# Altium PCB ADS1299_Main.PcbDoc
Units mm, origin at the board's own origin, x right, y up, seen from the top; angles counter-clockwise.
Board outline 156.34 x 83.19 mm, 6 copper layers (Top Layer, GND, AVSS, AVDD, DVDD, Bottom Layer), stack 0.816 mm thick; 64 components, 110 nets, 548 pads, 68 vias.
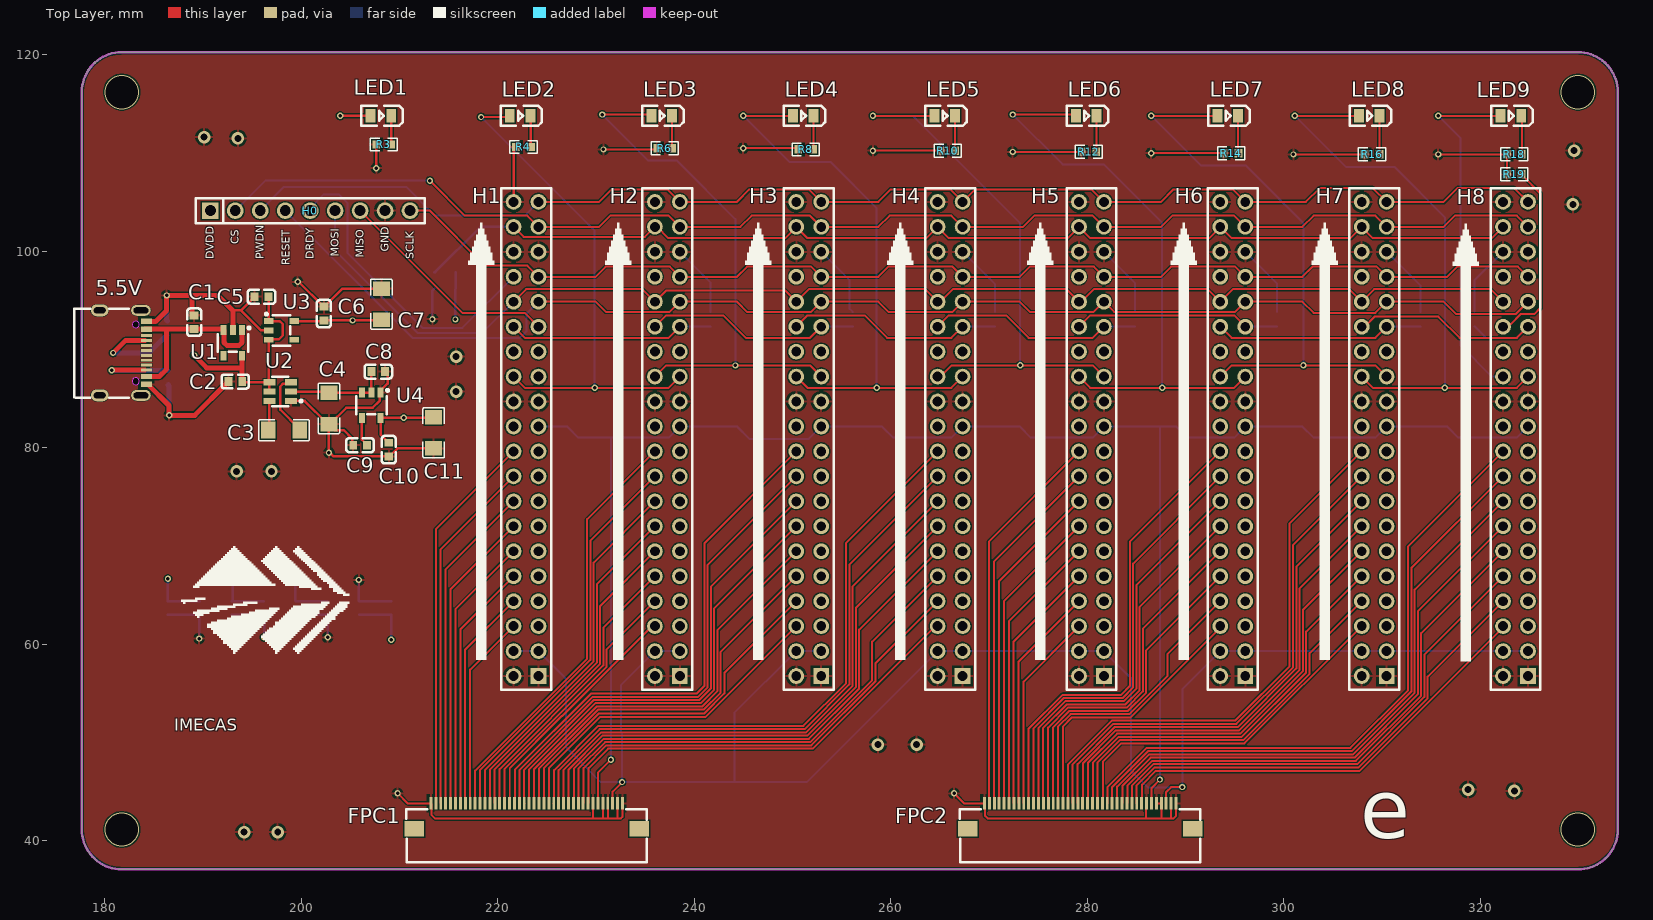
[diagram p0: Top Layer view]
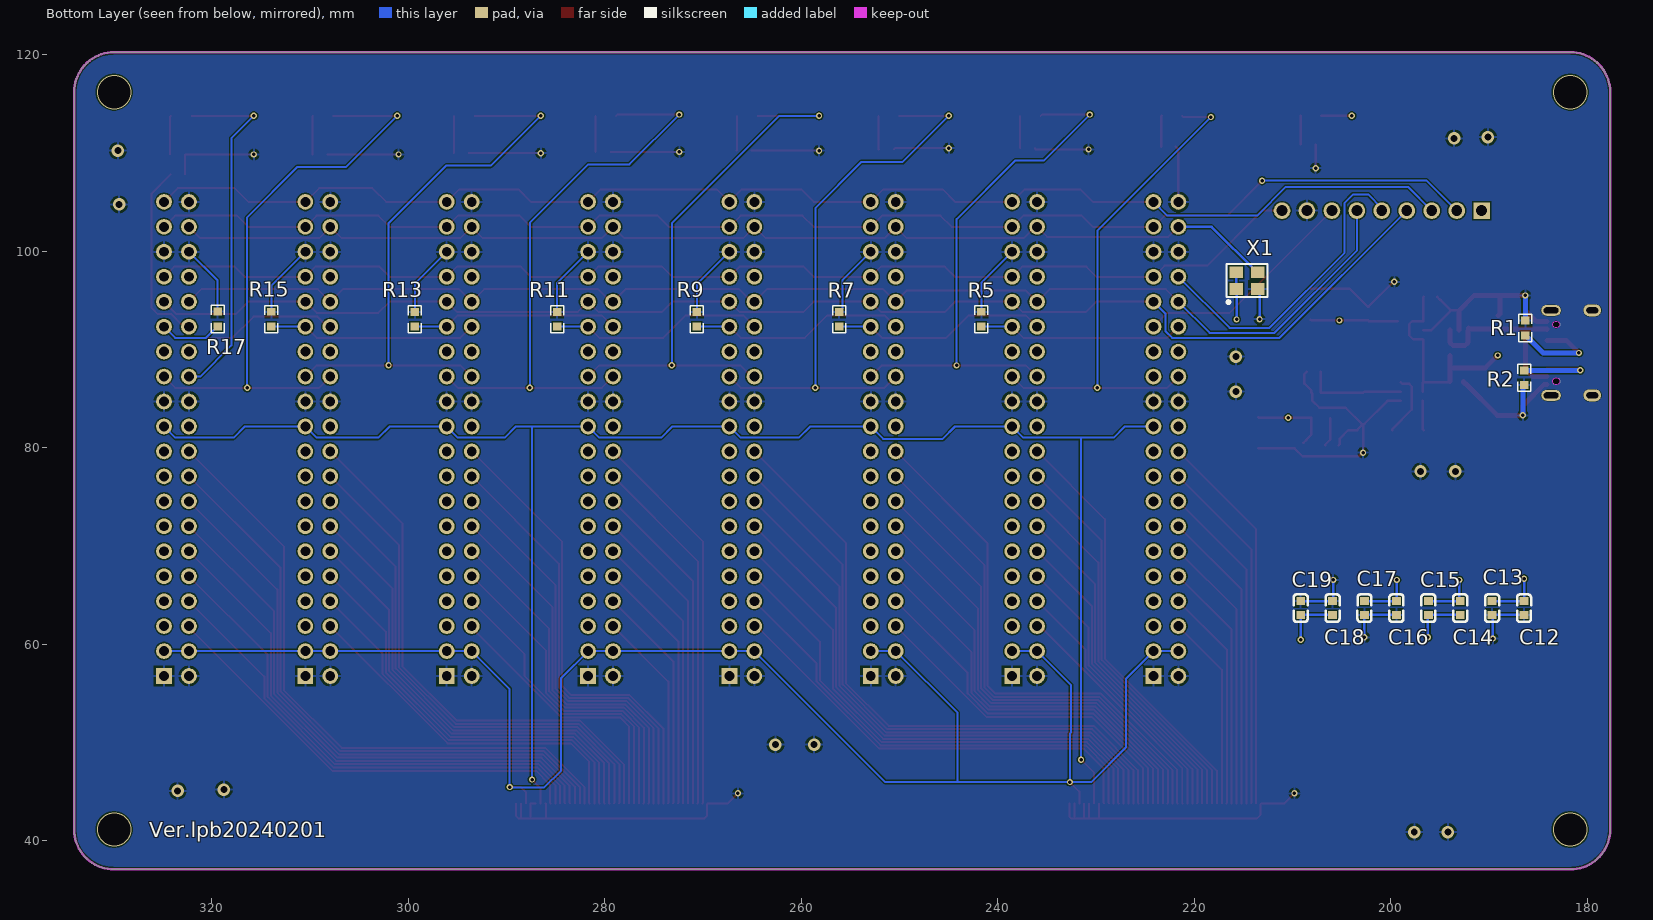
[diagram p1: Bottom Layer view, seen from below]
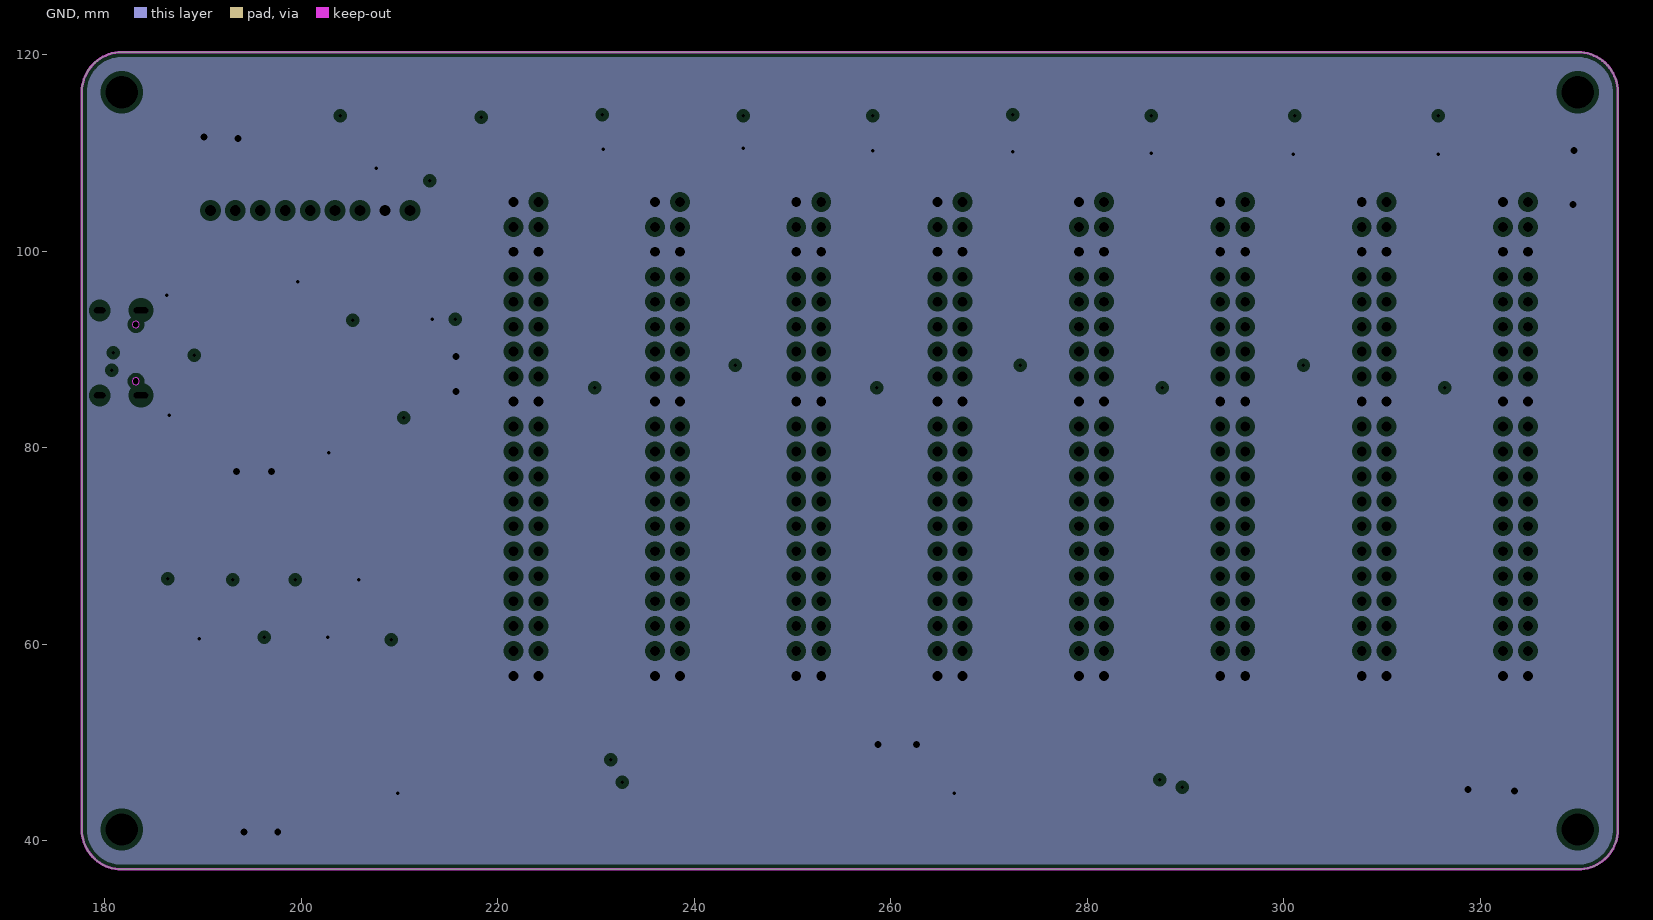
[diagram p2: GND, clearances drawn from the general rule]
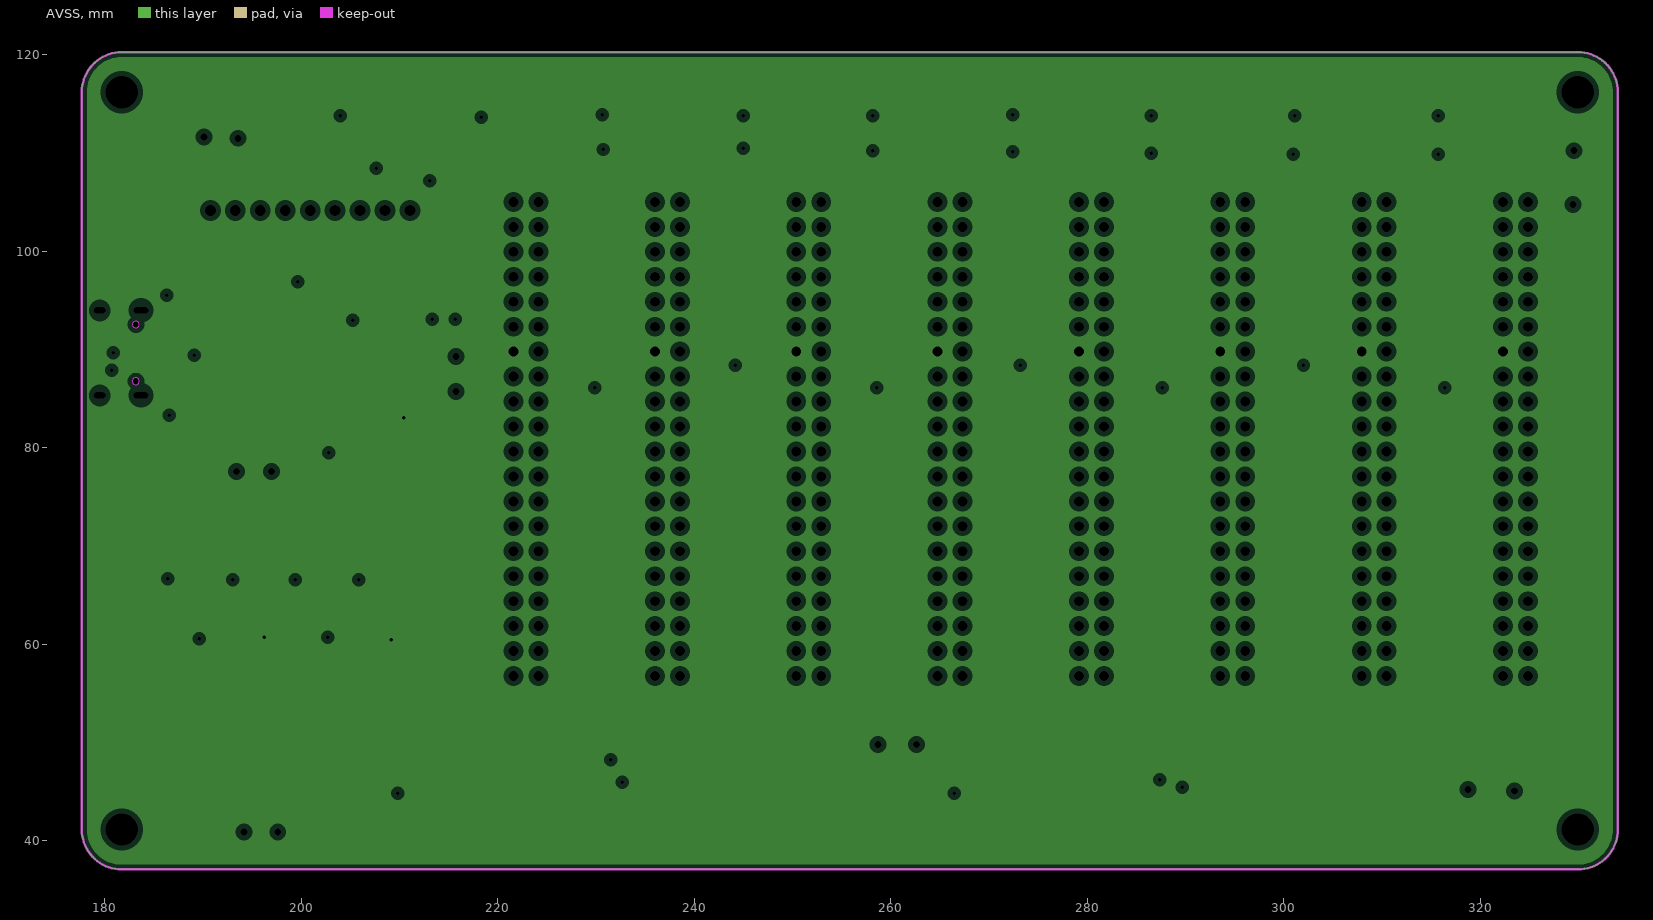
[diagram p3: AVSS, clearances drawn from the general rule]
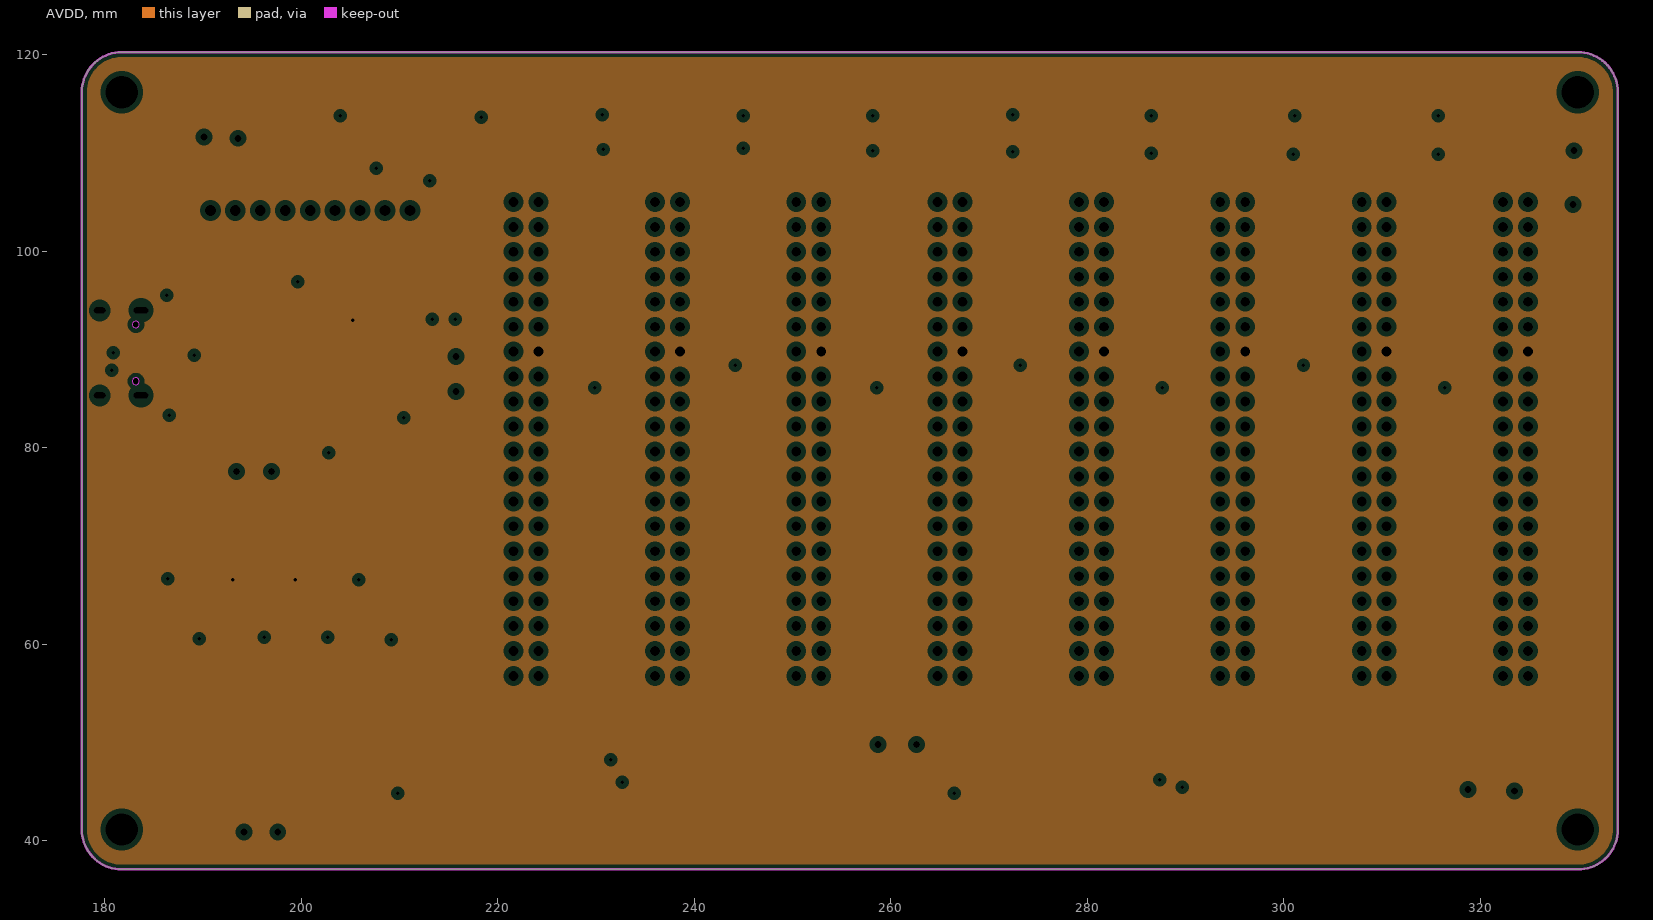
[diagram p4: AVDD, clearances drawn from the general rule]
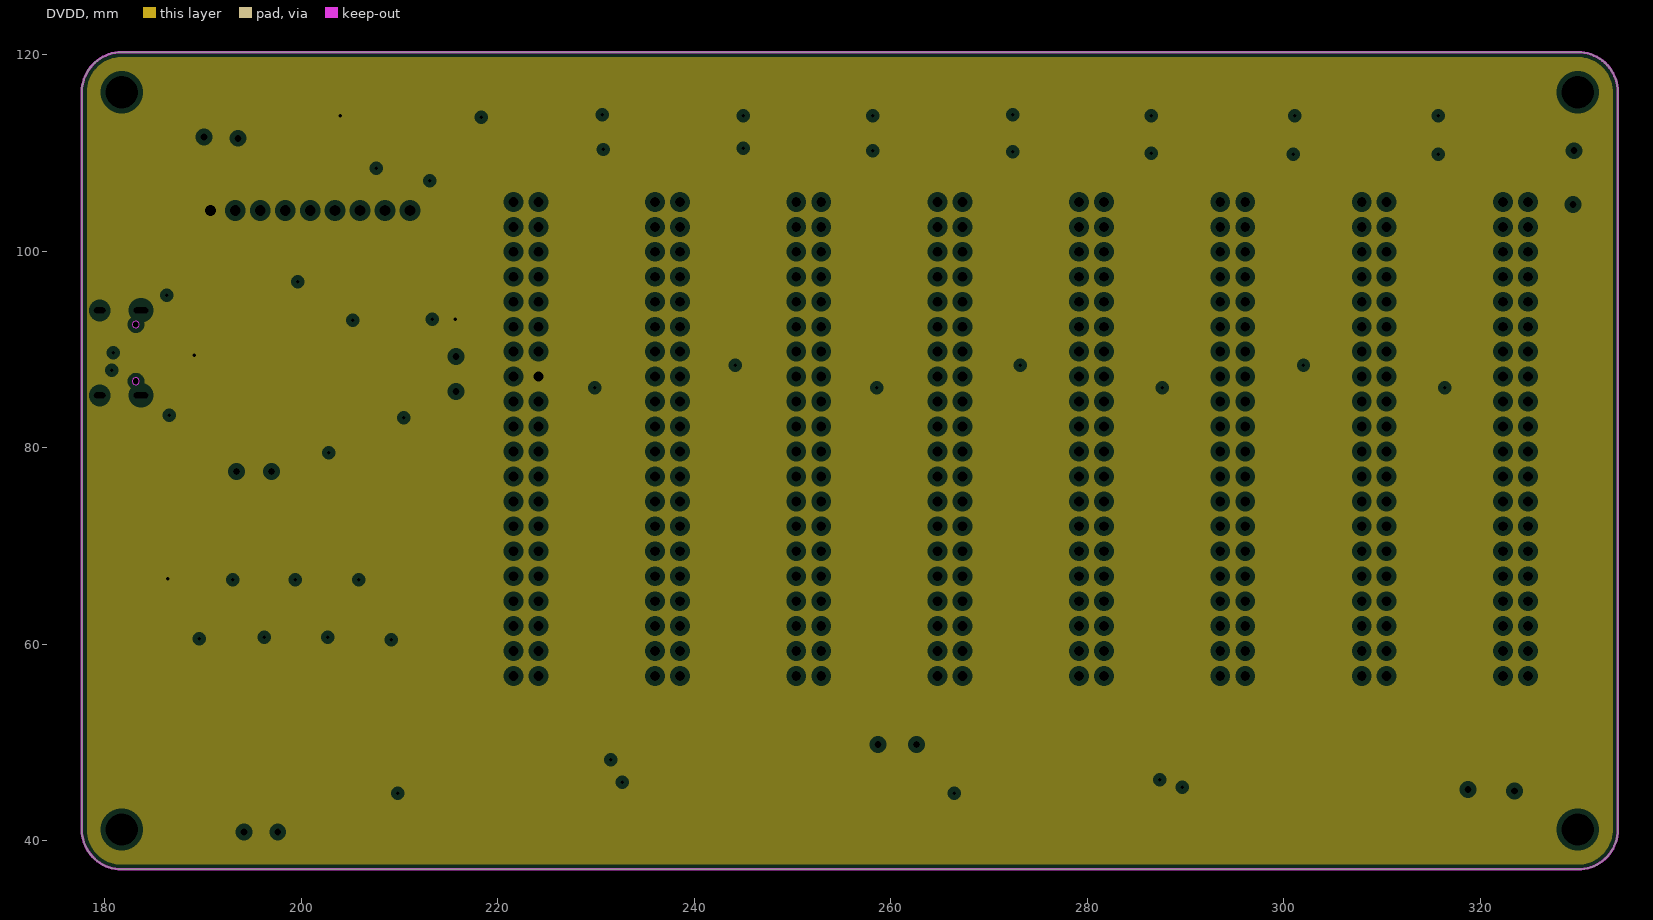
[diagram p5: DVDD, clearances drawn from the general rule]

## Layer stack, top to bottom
Top Solder: solder mask 0.0102, Solder Resist, Dk 3.5
Top Layer: signal copper 0.0356
Dielectric 2: prepreg 0.0711, PP-006, Dk 4.1
GND: plane copper 0.035, net GND
Dielectric 4: prepreg 0.0711, PP-006, Dk 4.1
AVSS: plane copper 0.035, net AVSS
Dielectric 1: dielectric 0.32, FR-4, Dk 4.8
AVDD: plane copper 0.035, net AVDD
Dielectric 5: prepreg 0.0711, PP-006, Dk 4.1
DVDD: plane copper 0.035, net DVDD
Dielectric 3: prepreg 0.0711, PP-006, Dk 4.1
Bottom Layer: signal copper 0.0356
Bottom Solder: solder mask 0.0102, Solder Resist, Dk 3.5

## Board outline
177.673,41.148 177.673,116.205 177.671,116.205 cw(c181.737,116.205) 181.737,120.271 181.737,120.269 329.942,120.269 329.944,120.271 cw(c329.944,116.205) 334.01,116.205 334.01,41.15 334.012,41.148 cw(c329.946,41.148) 329.946,37.082 181.737,37.082 cw(c181.737,41.148)

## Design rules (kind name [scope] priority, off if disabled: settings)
Clearance typec [HasFootprint('USB-C-SMD_TYPE-C-6PIN-2MD-073')] p1: gap=0.025 ignorepadtopadclearanceinfootprint=FALSE
Clearance fpc [HasFootprint('FPC-SMD_P0.50-40P_FGS-XJ-H2.0')] p2: gap=0.127 ignorepadtopadclearanceinfootprint=FALSE
Clearance [All] p3: gap=0.127 ignorepadtopadclearanceinfootprint=FALSE
PlaneClearance [All] p1: clearance=0.508
PlaneConnect [All] p1: planeconnectstyle=Relief reliefexpansion=0.508 reliefentries=4 reliefconductorwidth=0.254 reliefairgap=0.254
PolygonConnect [All] p1: connectstyle=Relief reliefconductorwidth=0.254 reliefentries=4 polygonreliefangle="90 Angle" airgapwidth=0.254
RoutingVias [All] p1: holewidth=0.356 width=0.635 viastyle="Through Hole" minholewidth=0.356 minwidth=0.635 maxholewidth=3.5 maxwidth=4.5
SolderMaskExpansion [All] p1: expansion=0.102 istentingtop=FALSE
Width [All] p1: maxlimit=0.508 minlimit=0.127 preferedwidth=0.203 minimp=50.000000 maximp=50.000000 favimp=50.000000
28 further rules are at their usual default settings.

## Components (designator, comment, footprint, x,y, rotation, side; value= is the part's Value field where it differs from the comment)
5.5V "TYPE-C 16PIN 2MD(073)" USB-C-SMD_TYPE-C-6PIN-2MD-073 181.864,89.662 r270 top (schematic designator USB1)
C1 "CL10A105KB8NNNC" C0603 189.103,92.775 r270 top value=1uF
C2 "CL10A105KB8NNNC" C0603 193.294,86.741 r0 top value=1uF
C3 "CL31A106KBHNNNE" C1206 198.247,81.788 r180 top value=10uF
C4 "CL31A106KBHNNNE" C1206 202.819,84.005 r90 top value=10uF
C5 "CL10A225KO8NNNC" C0603 195.961,95.377 r0 top value=2.2uF
C6 "CL10A225KO8NNNC" C0603 202.311,93.664 r90 top value=2.2uF
C7 "CL31A106KBHNNNE" C1206 208.153,94.615 r270 top value=10uF
C8 "CL10A225KO8NNNC" C0603 207.837,87.757 r180 top value=2.2uF
C9 "CC0603KRX7R9BB103" C0603 205.994,80.264 r0 top value=10nF
C10 "CL10A225KO8NNNC" C0603 208.915,79.818 r90 top value=2.2uF
C11 "CL31A106KBHNNNE" C1206 213.487,81.534 r90 top value=10uF
C12 "CL10A105KB8NNNC" C0603 186.436,63.692 r90 bottom value=1uF
C13 "CC0603KRX7R9BB104" C0603 189.684,63.692 r90 bottom value=100nF
C14 "CL10A105KB8NNNC" C0603 192.931,63.692 r90 bottom value=1uF
C15 "CC0603KRX7R9BB104" C0603 196.179,63.692 r90 bottom value=100nF
C16 "CL10A105KB8NNNC" C0603 199.426,63.692 r90 bottom value=1uF
C17 "CC0603KRX7R9BB104" C0603 202.674,63.692 r90 bottom value=100nF
C18 "CL10A105KB8NNNC" C0603 205.921,63.692 r90 bottom value=1uF
C19 "CC0603KRX7R9BB104" C0603 209.169,63.692 r90 bottom value=100nF
FPC1 "AFC01-S40FCA-00" FPC-SMD_P0.50-40P_FGS-XJ-H2.0 222.953,42.515 r180 top
FPC2 "AFC01-S40FCA-00" FPC-SMD_P0.50-40P_FGS-XJ-H2.0 279.293,42.515 r180 top
H0 "PZ254V-11-09P" HDR-TH_9P-P2.54-V-M 200.914,104.14 r0 top
H1 "PM254-2-20-Z-8.5" HDR-TH_40P-P2.54-V-F-R2-C20-S2.54 222.885,80.899 r90 top
H2 "PM254-2-20-Z-8.5" HDR-TH_40P-P2.54-V-F-R2-C20-S2.54 237.272,80.899 r90 top
H3 "PM254-2-20-Z-8.5" HDR-TH_40P-P2.54-V-F-R2-C20-S2.54 251.66,80.899 r90 top
H4 "PM254-2-20-Z-8.5" HDR-TH_40P-P2.54-V-F-R2-C20-S2.54 266.047,80.899 r90 top
H5 "PM254-2-20-Z-8.5" HDR-TH_40P-P2.54-V-F-R2-C20-S2.54 280.434,80.899 r90 top
H6 "PM254-2-20-Z-8.5" HDR-TH_40P-P2.54-V-F-R2-C20-S2.54 294.821,80.899 r90 top
H7 "PM254-2-20-Z-8.5" HDR-TH_40P-P2.54-V-F-R2-C20-S2.54 309.209,80.899 r90 top
H8 "PM254-2-20-Z-8.5" HDR-TH_40P-P2.54-V-F-R2-C20-S2.54 323.596,80.899 r90 top
LED1 "NCD0805R1" LED0805-R-RD 208.119,113.792 r180 top
LED2 "NCD0805R1" LED0805-R-RD 222.284,113.792 r180 top
LED3 "NCD0805R1" LED0805-R-RD 236.69,113.792 r180 top
LED4 "NCD0805R1" LED0805-R-RD 251.095,113.792 r180 top
LED5 "NCD0805R1" LED0805-R-RD 265.501,113.792 r180 top
LED6 "NCD0805R1" LED0805-R-RD 279.906,113.792 r180 top
LED7 "NCD0805R1" LED0805-R-RD 294.311,113.792 r180 top
LED8 "NCD0805R1" LED0805-R-RD 308.717,113.792 r180 top
LED9 "NCD0805R1" LED0805-R-RD 323.122,113.792 r180 top
R1 "0603WAF5101T5E" R0603 186.309,92.193 r270 bottom value=5.1kΩ
R2 "0603WAF5101T5E" R0603 186.436,87.131 r90 bottom value=5.1kΩ
R3 "0603WAF2201T5E" R0603 208.398,110.871 r0 top value=2.2kΩ
R4 "0603WAF2201T5E" R0603 222.622,110.617 r0 top value=2.2kΩ
R5 "0603WAF5101T5E" R0603 241.681,93.091 r270 bottom value=5.1kΩ
R6 "0603WAF2201T5E" R0603 236.991,110.49 r0 top value=2.2kΩ
R7 "0603WAF5101T5E" R0603 256.159,93.082 r270 bottom value=5.1kΩ
R8 "0603WAF2201T5E" R0603 251.342,110.363 r0 top value=2.2kΩ
R9 "0603WAF5101T5E" R0603 270.637,93.082 r270 bottom value=5.1kΩ
R10 "0603WAF2201T5E" R0603 265.82,110.236 r0 top value=2.2kΩ
R11 "0603WAF5101T5E" R0603 284.861,93.082 r270 bottom value=5.1kΩ
R12 "0603WAF2201T5E" R0603 280.171,110.109 r0 top value=2.2kΩ
R13 "0603WAF5101T5E" R0603 299.339,93.082 r270 bottom value=5.1kΩ
R14 "0603WAF2201T5E" R0603 294.649,109.982 r0 top value=2.2kΩ
R15 "0603WAF5101T5E" R0603 313.944,93.091 r270 bottom value=5.1kΩ
R16 "0603WAF2201T5E" R0603 308.991,109.855 r0 top value=2.2kΩ
R17 "0603WAF5101T5E" R0603 319.405,93.1 r270 bottom value=5.1kΩ
R18 "0603WAF2201T5E" R0603 323.478,109.855 r0 top value=2.2kΩ
R19 "0603WAF5101T5E" R0603 323.469,107.823 r0 top value=5.1kΩ
U1 "LP5907MFX-3.3/NOPB" SOT-23-5_L3.0-W1.7-P0.95-LS2.8-BR 193.04,90.678 r90 top
U2 "LM2664M6/NOPB" TSOT-23-6_L2.9-W1.6-P0.95-LS2.8-TL 197.866,85.725 r180 top
U3 "TLV70025DDCR" SOT-23-5_L3.0-W1.7-P0.95-LS2.8-BR 197.993,91.948 r180 top
U4 "TPS72325DBVR" SOT-23-5_L3.0-W1.7-P0.95-LS2.8-BR 207.137,84.328 r90 top
X1 "S3D2.048000B20F30T" OSC-SMD_4P-L3.2-W2.5-BL_SIT8008BI 214.63,97.028 r180 bottom value=2.048MHz

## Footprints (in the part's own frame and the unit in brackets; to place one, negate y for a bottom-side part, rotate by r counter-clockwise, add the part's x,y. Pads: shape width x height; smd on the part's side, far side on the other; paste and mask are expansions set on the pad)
C0603 [mm]
  rect 0.8x0.9 smd: 1(-0.7,0) 2(0.7,0)
  silkscreen extent -1.41,-0.71 1.39,0.72
C1206 [mm]
  rect 1.485x1.728 smd paste-100 mask+0.051: 1(-1.593,0) 2(1.593,0)
  silkscreen extent -2.56,-1.09 2.56,1.09
FPC-SMD_P0.50-40P_FGS-XJ-H2.0 [mm]
  rect 0.3x1.3 smd paste+0 mask+0.05: 1(9.75,-1.3) 2(9.25,-1.3) 3(8.75,-1.3) 4(8.25,-1.3) 5(7.75,-1.3) 6(7.25,-1.3) 7(6.75,-1.3) 8(6.25,-1.3) 9(5.75,-1.3) 10(5.25,-1.3) 11(4.75,-1.3) 12(4.25,-1.3) 13(3.75,-1.3) 14(3.25,-1.3) 15(2.75,-1.3) 16(2.25,-1.3) 17(1.75,-1.3) 18(1.25,-1.3) 19(0.75,-1.3) 20(0.25,-1.3) 21(-0.25,-1.3) 22(-0.75,-1.3) 23(-1.25,-1.3) 24(-1.75,-1.3) 25(-2.25,-1.3) 26(-2.75,-1.3) 27(-3.25,-1.3) 28(-3.75,-1.3) 29(-4.25,-1.3) 30(-4.75,-1.3) 31(-5.25,-1.3) 32(-5.75,-1.3) 33(-6.25,-1.3) 34(-6.75,-1.3) 35(-7.25,-1.3) 36(-7.75,-1.3) 37(-8.25,-1.3) 38(-8.75,-1.3) 39(-9.25,-1.3) 40(-9.75,-1.3)
  rect 2x1.6 smd: 41(-11.45,1.3) 42(11.45,1.3)
  silkscreen extent -12.2,-0.7 12.25,4.7
HDR-TH_9P-P2.54-V-M [mm]
  rect 1.7x1.7 hole 1.1: 1(-10.16,0)
  round 1.7 hole 1.1: 2(-7.62,0) 3(-5.08,0) 4(-2.54,0) 5(0,0) 6(2.54,0) 7(5.08,0) 8(7.62,0) 9(10.16,0)
  silkscreen extent -11.64,-1.27 11.64,1.27
HDR-TH_40P-P2.54-V-F-R2-C20-S2.54 [mm]
  rect 1.6x1.6 hole 1: 1(-24.13,-1.27)
  round 1.6 hole 1: 2(-24.13,1.27) 3(-21.59,-1.27) 4(-21.59,1.27) 5(-19.05,-1.27) 6(-19.05,1.27) 7(-16.51,-1.27) 8(-16.51,1.27) 9(-13.97,-1.27) 10(-13.97,1.27) 11(-11.43,-1.27) 12(-11.43,1.27) 13(-8.89,-1.27) 14(-8.89,1.27) 15(-6.35,-1.27) 16(-6.35,1.27) 17(-3.81,-1.27) 18(-3.81,1.27) 19(-1.27,-1.27) 20(-1.27,1.27) 21(1.27,-1.27) 22(1.27,1.27) 23(3.81,-1.27) 24(3.81,1.27) 25(6.35,-1.27) 26(6.35,1.27) 27(8.89,-1.27) 28(8.89,1.27) 29(11.43,-1.27) 30(11.43,1.27) 31(13.97,-1.27) 32(13.97,1.27) 33(16.51,-1.27) 34(16.51,1.27) 35(19.05,-1.27) 36(19.05,1.27) 37(21.59,-1.27) 38(21.59,1.27) 39(24.13,-1.27) 40(24.13,1.27)
  silkscreen extent -25.53,-2.54 25.53,2.54
LED0805-R-RD [mm]
  rect 1x1.4 smd: 1(1.05,0) 2(-1.05,0)
  silkscreen extent -2.22,-1.04 1.99,1.01
OSC-SMD_4P-L3.2-W2.5-BL_SIT8008BI [mm]
  rect 1.4x1.2 smd: 1(-1.1,-0.85) 2(1.1,-0.85) 3(1.1,0.85) 4(-1.1,0.85)
  silkscreen extent -2.1,-2.35 2.1,1.7
R0603 [mm]
  rect 0.806x0.864 smd paste-100 mask+0.051: 1(-0.753,0) 2(0.753,0)
  silkscreen extent -1.39,-0.66 1.39,0.66
SOT-23-5_L3.0-W1.7-P0.95-LS2.8-BR [mm]
  rect 1x0.6 smd: 1(1.3,-0.95) 2(1.3,0) 3(1.3,0.95) 4(-1.3,0.95) 5(-1.3,-0.95)
  silkscreen extent -0.9,-1.78 1.65,1.55
TSOT-23-6_L2.9-W1.6-P0.95-LS2.8-TL [mil]
  rect 48x24.5 smd: 1(-43.31,37.41) 2(-43.31,0.01) 3(-43.31,-37.41) 4(43.31,-37.41) 5(43.31,0.01) 6(43.31,37.41)
  silkscreen extent -89,-59 31,59
USB-C-SMD_TYPE-C-6PIN-2MD-073 [mm]
  rect 0.55x1.1 smd paste-100 mask+0.05: 1(-3.2,2.375) 2(-2.4,2.375) 11(2.4,2.375) 12(3.2,2.375)
  rect 0.3x1.1 smd paste-100 mask+0.05: 3(-1.75,2.375) 4(-1.25,2.375) 5(-0.75,2.375) 6(-0.25,2.375) 7(0.25,2.375) 8(0.75,2.375) 9(1.25,2.375) 10(1.75,2.375)
  oval 1.1x2 hole 0.6 slot 1.5 at 90 deg paste+0 mask+0.05: 13(-4.325,1.825) 14(4.325,1.825)
  oval 1.2x1.8 hole 0.6 slot 1.2 at 90 deg paste+0 mask+0.05: 13(-4.325,-2.375) 14(4.325,-2.375)
  Keep-Out Layer board cut-out: 3.24,1.305 3.24,1.375 3.187,1.503 3.088,1.602 2.96,1.655 2.821,1.655 2.692,1.602 2.593,1.503 2.54,1.375 2.54,1.305 2.54,1.235 2.593,1.107 2.692,1.008 2.821,0.955 2.96,0.955 3.088,1.008 3.187,1.107 3.24,1.235 3.24,1.305 3.24,1.305
  Keep-Out Layer board cut-out: -2.54,1.305 -2.54,1.375 -2.593,1.503 -2.692,1.602 -2.82,1.655 -2.96,1.655 -3.088,1.602 -3.187,1.503 -3.24,1.375 -3.24,1.305 -3.24,1.235 -3.187,1.107 -3.088,1.008 -2.96,0.955 -2.82,0.955 -2.692,1.008 -2.593,1.107 -2.54,1.235 -2.54,1.305 -2.54,1.305
  Multi-Layer pour cut-out: 3.24,1.305 3.24,1.375 3.187,1.503 3.088,1.602 2.96,1.655 2.821,1.655 2.692,1.602 2.593,1.503 2.54,1.375 2.54,1.305 2.54,1.235 2.593,1.107 2.692,1.008 2.821,0.955 2.96,0.955 3.088,1.008 3.187,1.107 3.24,1.235 3.24,1.305 3.24,1.305
  Multi-Layer pour cut-out: -2.54,1.305 -2.54,1.375 -2.593,1.503 -2.692,1.602 -2.82,1.655 -2.96,1.655 -3.088,1.602 -3.187,1.503 -3.24,1.375 -3.24,1.305 -3.24,1.235 -3.187,1.107 -3.088,1.008 -2.96,0.955 -2.82,0.955 -2.692,1.008 -2.593,1.107 -2.54,1.235 -2.54,1.305 -2.54,1.305
  silkscreen extent -4.5,-4.97 4.57,0.6

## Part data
5.5V: "typeC接口", Current Rating - Power (Max)=5A, JLCPCB Part Class="Extended Part", LCSC Part Name="Type-C 母 卧贴 带定位柱 不锈钢外壳 2次模顶", Manufacturer="SHOU HAN(首韩)", Operating Temperature Range=-25℃~+85℃
C1 C2 C12 C14 C16 C18: "1uf电容", JLCPCB Part Class="Basic Part", LCSC Part Name="1uF ±10% 50V", Manufacturer=SAMSUNG(三星), Temperature Coefficient=X5R, Tolerance=±10%, Voltage Rated=50V
C3 C4 C7 C11: "10uf电容", JLCPCB Part Class="Basic Part", LCSC Part Name="10uF ±10% 50V", Manufacturer=SAMSUNG(三星), Temperature Coefficient=X5R, Tolerance=±10%, Voltage Rated=50V
C5 C6 C8 C10: "2.2.uf电容", JLCPCB Part Class="Basic Part", LCSC Part Name="2.2uF ±10% 16V", Manufacturer=SAMSUNG(三星), Temperature Coefficient=X5R, Tolerance=±10%, Voltage Rated=16V
C9: "0.01uf电容", JLCPCB Part Class="Extended Part", LCSC Part Name="10nF ±10% 50V", Manufacturer=YAGEO(国巨), Temperature Coefficient=X7R, Tolerance=±10%, Voltage Rated=50V
C13 C15 C17 C19: "0.1uf电容", JLCPCB Part Class="Basic Part", LCSC Part Name="100nF ±10% 50V", Manufacturer=YAGEO(国巨), Temperature Coefficient=X7R, Tolerance=±10%, Voltage Rated=50V
FPC1 FPC2: "40P FPC", JLCPCB Part Class="Extended Part", LCSC Part Name="间距:0.5mm P数:40P 翻盖式 下接", Manufacturer=JS(钜硕电子)
H0: "1*9P", Color=黑色, Current Rating (Max)=-, JLCPCB Part Class="Extended Part", LCSC Part Name="间距:2.54mm 1x9P 直插 方针", Manufacturer=XFCN(兴飞), Operating Temperature Range=-40℃~+105℃
H1 H2 H3 H4 H5 H6 H7 H8: "2*20P母", Current Rating (Max)=3A, JLCPCB Part Class="Extended Part", LCSC Part Name="间距:2.54mm 2x20P 直插", Manufacturer=HCTL(华灿天禄), Operating Temperature Range=-40℃~+105℃, Voltage Rating (Max)=-
LED1 LED2 LED3 LED4 LED5 LED6 LED7 LED8 LED9: "led", Color Temperature=-, Emitted Color=红色, Forward Current=20mA, Forward Voltage (VF)=1.6V~2.6V, JLCPCB Part Class="Basic Part", LCSC Part Name="红灯 0805红灯   正贴", Lens Color=无色透明, Manufacturer=国星光电, Operating Temperature=-30℃~+85℃, Power Dissipation=65mW
R1 R2 R5 R7 R9 R11 R13 R15 R17 R19: "5.1k电阻", JLCPCB Part Class="Basic Part", LCSC Part Name="5.1kΩ ±1% 100mW 厚膜电阻", Manufacturer=UNI-ROYAL(厚声), Operating Temperature Range=-55℃~+155℃, Overload Voltage (Max)=75V, Power(Watts)=100mW, Temperature Coefficient=±100ppm/℃, Tolerance=±1%
R3 R4 R6 R8 R10 R12 R14 R16 R18: "2.2k电阻", JLCPCB Part Class="Basic Part", LCSC Part Name="2.2kΩ ±1% 100mW 厚膜电阻", Manufacturer=UNI-ROYAL(厚声), Operating Temperature Range=-55℃~+155℃, Overload Voltage (Max)=75V, Power(Watts)=100mW, Temperature Coefficient=±100ppm/℃, Tolerance=±1%
U1: "3.3v线性稳压器", Dropout Voltage=250mV@(250mA), JLCPCB Part Class="Extended Part", LCSC Part Name="输入5.5V 输出3.3V 250mA", Manufacturer=TI(德州仪器), Maximum Input Voltage=5.5V, Operating Temperature=-40℃~+125℃, Output Current=250mA, Output Voltage=3.3V, Power Supply Rejection Ratio (PSRR)=90dB, Quiescent Current (Ground Current)=25uA
U2: "反相器", Input Voltage=1.8V~5.5V, JLCPCB Part Class="Extended Part", LCSC Part Name="输入1.8V~5.5V 40mA", Manufacturer=TI(德州仪器), Operating Temperature=-40℃~+85℃@(TJ), Output Current (Max)=40mA, Switching Frequency=80kHz
U3: "正压稳压器2.5v", Dropout Voltage=250mV@(200mA), JLCPCB Part Class="Extended Part", LCSC Part Name="输入5.5V 输出2.5V 200mA", Manufacturer=TI(德州仪器), Maximum Input Voltage=5.5V, Operating Temperature=-40℃~+125℃@(Tj), Output Current=200mA, Output Voltage=2.5V, Power Supply Rejection Ratio (PSRR)=68dB@(1kHz), Quiescent Current (Ground Current)=55uA
U4: "负压稳压器-2.5v", Dropout Voltage=500mV@(200mA), JLCPCB Part Class="Extended Part", LCSC Part Name="输入10V 输出2.5V 200mA", Manufacturer=TI(德州仪器), Maximum Input Voltage=10V, Operating Temperature=-40℃~+125℃, Output Current=200mA, Output Voltage=2.5V, Power Supply Rejection Ratio (PSRR)=65dB, Quiescent Current (Ground Current)=200uA
X1: "2.048M有源晶振", Frequency Stability=±20ppm, JLCPCB Part Class="Extended Part", LCSC Part Name="2.048MHz ±20ppm 3.3V CMOS", Manufacturer=SCTF(星通时频), Operating Temperature=-40℃~+85℃, Supply Current (Max)=10mA, Supply Voltage=3.3V

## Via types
v1: diameter 0.635, hole 0.356, Top Layer to Bottom Layer, 50 vias
v2: diameter 1.27, hole 0.711, Top Layer to Bottom Layer, 14 vias
v3: diameter 3.5, hole 3.3, Top Layer to Bottom Layer, 4 vias

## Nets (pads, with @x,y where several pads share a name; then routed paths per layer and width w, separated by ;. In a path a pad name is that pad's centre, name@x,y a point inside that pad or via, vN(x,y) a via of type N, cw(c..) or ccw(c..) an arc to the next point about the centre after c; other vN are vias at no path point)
AVDD: C6.1 C7.2 C14.2 C15.2 C16.2 C17.2 H1.27 H2.27 H3.27 H4.27 H5.27 H6.27 H7.27 H8.27 U3.5 | length 19.8
  Top Layer w0.254: U3.5 202.245,92.898 C6.1 v1(205.232,92.964) 208.095,92.964 C7.2
  Bottom Layer w0.254: v1(193.04,66.548) 193.04,64.501 C14.2 C15.2 ; v1(199.39,66.548) 199.39,64.428 C16.2 C17.2
AVSS: C10.2 C11.2 C14.1 C15.1 C18.1 C19.1 H1.28 H2.28 H3.28 H4.28 H5.28 H6.28 H7.28 H8.28 U4.5 | length 19.6
  Top Layer w0.254: C10.2 208.865,80.518 208.592,80.791 208.592,80.841 208.117,81.316 208.117,83.058 v1(210.439,83.058) 213.418,83.058 C11.2
  Bottom Layer w0.254: C14.1 C15.1 196.215,62.956 v1(196.215,60.706) ; C18.1 C19.1 v1(209.169,60.452)
BIAS: FPC1.38 FPC2.38 H1.3 H1.4 H2.3 H2.4 H3.3 H3.4 H4.3 H4.4 H5.3 H5.4 H6.3 H6.4 H7.3 H7.4 H8.3 H8.4 | length 182.6
  Top Layer w0.203: FPC1.38 231.703,45.013 v1(232.664,45.974) ; FPC2.38 288.043,44.965 288.544,45.466 v1(289.687,45.466)
  Bottom Layer w0.203: H1.4 H1.3 226.949,56.515 226.949,49.53 230.505,45.974 v1(232.664,45.974) 244.094,45.974 ; v1@232.63,46.008 232.63,50.938 232.537,51.031 232.537,55.844 H2.4 H2.3 ; H3.3 H3.4 244.094,53.013 244.094,45.974 ; H8.3 H8.4 H7.3 H7.4 H6.3 H6.4 289.687,55.445 v1(289.687,45.466) 289.649,45.428 286.169,45.428 284.446,47.151 284.446,56.567 H5.3 H5.4 H4.3 H4.4 251.442,45.974 244.094,45.974
DVDD: C2.2 C5.2 C12.2 C13.2 H0.1 H1.25 LED1.1 U1.5 U2.4 U2.5 U3.1 U3.3 X1.1 X1.4 | length 36.4
  Top Layer w0.254: C2.2 194.06,86.675 U2.4 ; C5.2 196.693,95.345 U3.1 197.805,92.898 198.12,92.583 198.12,91.44 197.714,91.034 196.729,91.034 U3.3 196.693,86.748 U2.4 ; U2.5 U2.4 ; v1(203.962,113.792) LED1.1
  Top Layer w0.508: v1(189.103,89.408) 190.373,88.138 193.99,88.138 U1.5 ; 193.992,88.138 193.992,86.743 C2.2
  Bottom Layer w0.254: v1(186.436,66.675) C12.2 C13.2 ; v1(215.694,93.067) 215.694,96.142 X1.1 X1.4
DVSS: C4.2 C8.2 U2.2 U4.2 U4.3 | length 10.4
  Top Layer w0.254: U2.2 202.692,85.725 C4.2 206.157,85.598 U4.3 U4.2 C8.2
GND: 5.5V.1 5.5V.12 C1.1 C2.1 C4.1 C5.1 C6.2 C7.1 C8.1 C9.1 C10.1 C11.1 C12.1 C13.1 C16.1 C17.1 C18.2 C19.2 FPC1.1 FPC1.34 FPC1.36 FPC1.37 FPC1.39 FPC1.40 FPC2.1 FPC2.34 FPC2.36 FPC2.37 FPC2.39 FPC2.40 H0.8 H1.1 H1.2 H1.23 H1.24 H1.35 H1.36 H1.40 H2.1 H2.2 H2.23 H2.24 H2.35 H2.36 H2.40 H3.1 H3.2 H3.23 H3.24 H3.35 H3.36 H3.40 H4.1 H4.2 H4.23 H4.24 H4.35 H4.36 H4.40 H5.1 H5.2 H5.23 H5.24 H5.35 H5.36 H5.40 H6.1 H6.2 H6.23 H6.24 H6.35 H6.36 H6.40 H7.1 H7.2 H7.23 H7.24 H7.35 H7.36 H7.40 H8.1 H8.2 H8.23 H8.24 H8.35 H8.36 H8.40 R1.1 R2.1 R3.1 R4.1 R5.1 R6.1 R7.1 R8.1 R9.1 R10.1 R11.1 R12.1 R13.1 R14.1 R15.1 R16.1 R17.1 R18.1 R19.1 U1.2 U2.1 U3.2 U4.1 X1.2 | length 273.9
  Top Layer w0.203: v1(209.804,44.831) 210.82,43.815 FPC1.1 213.251,43.767 213.251,42.654 213.614,42.291 229.743,42.291 ; FPC1.34 229.703,42.331 229.743,42.291 ; 230.703,42.368 FPC1.36 ; v1(230.759,110.363) 236.11,110.363 R6.1 ; FPC1.37 231.203,42.358 231.136,42.291 ; FPC1.39 232.203,42.338 232.156,42.291 ; FPC1.40 232.703,42.457 232.537,42.291 232.156,42.291 ; v1(244.983,110.49) 250.461,110.49 R8.1 ; v1(258.191,110.236) R10.1 ; v1(266.446,44.831) 267.462,43.815 FPC2.1 269.591,43.767 269.591,42.575 269.875,42.291 286.004,42.291 ; v1(272.415,110.109) R12.1 ; FPC2.34 286.004,43.776 286.004,42.291 ; v1(286.512,109.982) R14.1 ; FPC2.36 FPC2.37 287.543,42.306 287.528,42.291 ; FPC2.39 288.543,42.292 288.544,42.291 ; FPC2.40 289.043,42.536 288.798,42.291 288.544,42.291 ; v1(300.99,109.855) R16.1 ; v1(315.722,109.855) R18.1 322.716,109.846 R19.1 ; 229.743,42.291 231.136,42.291 ; 231.136,42.291 232.156,42.291 ; 286.004,42.291 287.528,42.291 ; 287.528,42.291 288.544,42.291
  Top Layer w0.254: 193.04,93.98 193.864,93.98 ; C5.1 195.261,95.327 194.988,95.054 194.938,95.054 193.864,93.98 ; U3.2 195.896,91.948 193.864,93.98 ; U2.1 200.335,84.775 202.698,82.413 C4.1 ; v1(199.644,96.901) 199.724,96.901 202.261,94.364 C6.2 202.361,94.364 204.205,96.208 C7.1 ; C4.1@202.94,82.413 204.602,84.074 207.264,84.074 207.974,84.784 207.974,85.515 U4.1 208.087,85.828 208.788,86.529 208.788,87.506 C8.1 ; C9.1 205.185,80.373 205.185,80.946 204.334,81.797 203.435,81.797 C4.1 ; v1(207.645,108.458) R3.1 ; C11.1 209.788,79.941 208.965,79.118 C10.1 203.306,79.118 202.922,79.502 v1(202.819,79.502) C4.1 ; H1.40 221.615,110.363 R4.1
  Top Layer w0.508: 5.5V.1@184.112,92.862 185.191,92.862 186.285,93.956 186.285,95.48 v1(186.309,95.504) 186.333,95.48 188.907,95.48 ; 5.5V.12@184.133,86.441 184.112,86.462 184.387,86.462 186.539,84.31 186.539,83.336 v1(186.563,83.312) 189.165,83.312 192.398,86.545 192.448,86.545 192.594,86.691 C2.1 ; C1.1 189.053,93.475 188.907,93.621 188.907,95.48 ; U1.2 193.04,93.98 191.54,95.48 188.907,95.48
  Bottom Layer w0.203: H2.35 241.681,96.81 R5.1 ; H3.35 255.829,97.05 255.829,94.137 256.13,93.836 R7.1 ; H4.35 270.637,96.629 R9.1 ; H5.35 284.861,96.792 R11.1 ; H6.35 299.339,96.701 R13.1 ; H7.35 313.944,96.484 R15.1 ; R17.1 319.405,97.028 H8.36
  Bottom Layer w0.254: C12.1 C13.1 189.611,62.919 v1(189.611,60.579) ; C16.1 C17.1 202.692,62.974 v1(202.692,60.706) ; v1(205.867,66.548) 205.867,64.446 C18.2 C19.2 ; v1(213.36,93.091) 213.36,96.008 X1.2
  Bottom Layer w0.508: v1(186.309,95.504) R1.1 R1.1@186.373,92.883 ; R2.1@186.5,86.441 R2.1 186.539,86.275 186.539,83.336 v1(186.563,83.312)
  other v2: 194.183,40.894 197.612,40.894 323.469,45.085 318.77,45.212 258.699,49.784 262.636,49.784 193.421,77.597 196.977,77.597 215.773,85.725 215.773,89.281 329.438,104.775 329.565,110.236 193.548,111.506 190.119,111.633
NetC3_1: C3.1 U2.3 | length 6.5
  Top Layer w0.254: U2.3 198.819,86.528 198.161,86.528 197.866,86.233 197.866,83.883 199.84,81.909 C3.1
NetC3_2: C3.2 U2.6 | length 3
  Top Layer w0.254: C3.2 196.766,81.9 U2.6
NetC9_2: C9.2 U4.4 | length 3
  Top Layer w0.254: U4.4 206.187,80.821 206.694,80.314 C9.2
NetFPC1_2: FPC1.2 H1.20 | length 39.1
  Top Layer w0.203: FPC1.2 213.695,43.823 213.695,71.709 H1.20
NetFPC1_3: FPC1.3 H1.18 | length 36.4
  Top Layer w0.203: FPC1.3 214.195,43.823 214.195,69.669 H1.18
NetFPC1_4: FPC1.4 H1.16 | length 33.6
  Top Layer w0.203: FPC1.4 214.695,43.823 214.695,67.629 H1.16
NetFPC1_5: FPC1.5 H1.14 | length 30.9
  Top Layer w0.203: FPC1.5 215.195,43.823 215.195,65.589 H1.14
NetFPC1_6: FPC1.6 H1.12 | length 28.1
  Top Layer w0.203: FPC1.6 215.695,43.823 215.695,63.549 H1.12
NetFPC1_7: FPC1.7 H1.10 | length 25.4
  Top Layer w0.203: FPC1.7 216.195,43.823 216.195,61.509 H1.10
NetFPC1_8: FPC1.8 H1.8 | length 22.6
  Top Layer w0.203: FPC1.8 216.695,43.823 216.695,59.469 H1.8
NetFPC1_9: FPC1.9 H1.6 | length 19.9
  Top Layer w0.203: FPC1.9 217.195,43.823 217.195,57.429 H1.6
NetFPC1_10: FPC1.10 H2.20 | length 43.4
  Top Layer w0.203: FPC1.10 217.695,43.823 217.695,47.134 229.108,58.547 229.108,72.735 H2.20
NetFPC1_11: FPC1.11 H2.18 | length 40.7
  Top Layer w0.203: FPC1.11 218.195,43.823 218.195,47.167 229.438,58.41 229.438,70.525 H2.18
NetFPC1_12: FPC1.12 H2.16 | length 37.9
  Top Layer w0.203: FPC1.12 218.695,43.823 218.695,47.2 229.768,58.273 229.768,68.315 H2.16
NetFPC1_13: FPC1.13 H2.14 | length 35.2
  Top Layer w0.203: FPC1.13 219.195,43.823 219.195,47.233 230.099,58.137 230.099,66.105 H2.14
NetFPC1_14: FPC1.14 H2.12 | length 32.4
  Top Layer w0.203: FPC1.14 219.695,43.823 219.695,47.266 230.429,58 230.429,63.896 H2.12
NetFPC1_15: FPC1.15 H2.10 | length 29.7
  Top Layer w0.203: FPC1.15 220.195,43.823 220.195,47.299 230.759,57.863 230.759,61.686 H2.10
NetFPC1_16: FPC1.16 H2.8 | length 26.9
  Top Layer w0.203: FPC1.16 220.695,43.823 220.695,47.332 231.089,57.726 231.089,59.476 H2.8
NetFPC1_17: FPC1.17 H2.6 | length 24.4
  Top Layer w0.203: FPC1.17 221.226,43.838 221.226,47.396 226.535,52.705 226.56,52.705 235.704,61.849 H2.6
NetFPC1_18: FPC1.18 H3.20 | length 54
  Top Layer w0.203: FPC1.18 221.743,43.855 221.743,47.212 229.522,54.991 240.263,54.991 241.046,55.774 241.046,70.285 H3.20
NetFPC1_19: FPC1.19 H3.18 | length 51.2
  Top Layer w0.203: FPC1.19 222.195,43.823 222.195,47.197 229.659,54.661 240.4,54.661 241.376,55.637 241.376,68.076 H3.18
NetFPC1_20: FPC1.20 H3.16 | length 48.5
  Top Layer w0.203: FPC1.20 222.695,43.823 222.695,47.23 229.796,54.331 240.536,54.331 241.706,55.501 241.706,65.866 H3.16
NetFPC1_21: FPC1.21 H3.14 | length 45.8
  Top Layer w0.203: FPC1.21 223.195,43.823 223.195,47.263 229.933,54 240.673,54 242.037,55.364 242.037,63.656 H3.14
NetFPC1_22: FPC1.22 H3.12 | length 43
  Top Layer w0.203: FPC1.22 223.695,43.823 223.695,47.296 230.069,53.67 240.81,53.67 242.367,55.227 242.367,61.446 H3.12
NetFPC1_23: FPC1.23 H3.10 | length 40.3
  Top Layer w0.203: FPC1.23 224.195,43.823 224.195,47.329 230.206,53.34 240.947,53.34 242.697,55.09 242.697,59.236 H3.10
NetFPC1_24: FPC1.24 H3.8 | length 37.5
  Top Layer w0.203: FPC1.24 224.703,47.37 230.288,52.955 241.029,52.955 243.078,55.004 243.078,57.077 H3.8
NetFPC1_25: FPC1.25 H3.6 | length 34.8
  Top Layer w0.203: FPC1.25 225.203,47.403 230.425,52.625 241.165,52.625 H3.6
NetFPC1_26: FPC1.26 H4.20 | length 64.2
  Top Layer w0.203: FPC1.26 225.752,43.863 225.752,47.197 230.243,51.689 251.112,51.689 255.473,56.05 255.473,70.325 H4.20
NetFPC1_27: FPC1.27 H4.18 | length 61.5
  Top Layer w0.203: FPC1.27 226.203,47.182 230.38,51.359 251.249,51.359 255.803,55.913 255.803,68.116 H4.18
NetFPC1_28: FPC1.28 H4.16 | length 58.7
  Top Layer w0.203: FPC1.28 226.703,47.215 230.517,51.029 251.386,51.029 256.134,55.776 256.134,65.906 H4.16
NetFPC1_29: FPC1.29 H4.14 | length 56
  Top Layer w0.203: FPC1.29 227.203,47.248 230.653,50.698 251.523,50.698 256.464,55.64 256.464,63.696 H4.14
NetFPC1_30: FPC1.30 H4.12 | length 53.3
  Top Layer w0.203: FPC1.30 227.679,43.815 227.752,43.887 227.752,47.329 230.79,50.368 251.659,50.368 256.794,55.503 256.794,61.486 H4.12
NetFPC1_31: FPC1.31 H4.10 | length 50.5
  Top Layer w0.203: FPC1.31 228.203,47.314 230.927,50.038 251.796,50.038 258.12,56.362 258.12,60.273 H4.10
NetFPC1_32: FPC1.32 H4.8 | length 47.7
  Top Layer w0.203: FPC1.32 228.752,43.863 228.752,47.396 231.064,49.708 251.933,49.708 258.451,56.226 258.451,58.063 H4.8
NetFPC1_33: FPC1.33 H4.6 | length 45.1
  Top Layer w0.203: FPC1.33 229.251,43.863 229.251,47.387 231.242,49.378 252.07,49.378 264.541,61.849 H4.6
NetFPC2_2: FPC2.2 H5.20 | length 39.6
  Top Layer w0.203: FPC2.2 270.023,43.835 270.023,70.488 H5.20
NetFPC2_3: FPC2.3 H5.18 | length 36.9
  Top Layer w0.203: FPC2.3 270.523,43.835 270.523,68.448 H5.18
NetFPC2_4: FPC2.4 H5.16 | length 34.1
  Top Layer w0.203: FPC2.4 271.023,43.835 271.023,66.408 H5.16
NetFPC2_5: FPC2.5 H5.14 | length 31.4
  Top Layer w0.203: FPC2.5 271.523,43.835 271.523,64.368 H5.14
NetFPC2_6: FPC2.6 H5.12 | length 28.6
  Top Layer w0.203: FPC2.6 272.023,43.835 272.023,62.328 H5.12
NetFPC2_7: FPC2.7 H5.10 | length 25.9
  Top Layer w0.203: FPC2.7 272.523,43.835 272.523,60.288 H5.10
NetFPC2_8: FPC2.8 H5.8 | length 23.1
  Top Layer w0.203: FPC2.8 273.023,43.835 273.023,58.248 H5.8
NetFPC2_9: FPC2.9 H5.6 | length 20.4
  Top Layer w0.203: FPC2.9 273.523,43.835 273.523,56.208 H5.6
NetFPC2_10: FPC2.10 H6.20 | length 47.4
  Top Layer w0.203: FPC2.10 274.023,43.835 274.023,51.392 277.495,54.864 283.464,54.864 284.353,55.753 284.353,70.431 H6.20
NetFPC2_11: FPC2.11 H6.18 | length 44.7
  Top Layer w0.203: FPC2.11 274.523,43.835 274.523,51.425 277.632,54.534 283.601,54.534 284.683,55.616 284.683,68.221 H6.18
NetFPC2_12: FPC2.12 H6.16 | length 41.9
  Top Layer w0.203: FPC2.12 275.023,43.835 275.023,51.458 277.769,54.204 283.738,54.204 285.013,55.479 285.013,66.011 H6.16
NetFPC2_13: FPC2.13 H6.14 | length 39.2
  Top Layer w0.203: FPC2.13 275.523,43.835 275.523,51.491 277.905,53.873 283.874,53.873 285.344,55.343 285.344,63.801 H6.14
NetFPC2_14: FPC2.14 H6.12 | length 36.4
  Top Layer w0.203: FPC2.14 276.023,43.835 276.023,51.524 278.042,53.543 284.011,53.543 285.674,55.206 285.674,61.591 H6.12
NetFPC2_15: FPC2.15 H6.10 | length 33.7
  Top Layer w0.203: FPC2.15 276.523,43.835 276.523,51.557 278.179,53.213 284.148,53.213 286.004,55.069 286.004,59.382 H6.10
NetFPC2_16: FPC2.16 H6.8 | length 30.9
  Top Layer w0.203: FPC2.16 277.023,43.835 277.023,51.59 278.316,52.883 284.285,52.883 288.182,56.78 288.182,59.02 H6.8
NetFPC2_17: FPC2.17 H6.6 | length 28.2
  Top Layer w0.203: FPC2.17 277.523,43.835 277.523,51.623 278.452,52.553 284.421,52.553 293.551,61.683 H6.6
NetFPC2_18: FPC2.18 H7.20 | length 55.6
  Top Layer w0.203: FPC2.18 278.023,43.835 278.023,47.739 282.507,52.222 295.046,52.222 300.609,57.785 300.609,72.299 H7.20
NetFPC2_19: FPC2.19 H7.18 | length 52.8
  Top Layer w0.203: FPC2.19 278.523,43.835 278.523,47.772 282.643,51.892 295.183,51.892 300.97,57.679 300.97,70.12 H7.18
NetFPC2_20: FPC2.20 H7.16 | length 50.1
  Top Layer w0.203: FPC2.20 279.023,43.835 279.023,47.805 282.78,51.562 295.32,51.562 301.3,57.542 301.3,59.121 301.3,67.911 H7.16
NetFPC2_21: FPC2.21 H7.14 | length 47.3
  Top Layer w0.203: FPC2.21 279.571,43.843 279.571,47.886 282.917,51.232 295.457,51.232 301.631,57.406 301.631,58.295 301.631,65.701 H7.14
NetFPC2_22: FPC2.22 H7.12 | length 44.6
  Top Layer w0.203: FPC2.22 280.071,43.843 280.071,47.919 283.054,50.902 295.593,50.902 301.961,57.269 301.961,58.158 301.961,63.491 H7.12
NetFPC2_23: FPC2.23 H7.10 | length 41.8
  Top Layer w0.203: FPC2.23 280.571,43.843 280.571,47.952 283.19,50.571 295.73,50.571 302.291,57.132 302.291,58.021 302.291,61.281 H7.10
NetFPC2_24: FPC2.24 H7.8 | length 39.1
  Top Layer w0.203: FPC2.24 281.043,47.957 283.327,50.241 295.867,50.241 302.641,57.015 302.641,59.091 H7.8
NetFPC2_25: FPC2.25 H7.6 | length 36.3
  Top Layer w0.203: FPC2.25 281.552,43.815 281.591,43.855 281.591,48.038 283.464,49.911 296.004,49.911 307.939,61.846 H7.6
NetFPC2_26: FPC2.26 H8.20 | length 64.7
  Top Layer w0.203: FPC2.26 282.043,45.442 286.055,49.454 306.797,49.454 312.674,55.331 312.674,69.977 H8.20
NetFPC2_27: FPC2.27 H8.18 | length 61.9
  Top Layer w0.203: FPC2.27 282.543,45.475 286.192,49.124 306.934,49.124 313.004,55.194 313.004,67.767 H8.18
NetFPC2_28: FPC2.28 H8.16 | length 59.2
  Top Layer w0.203: FPC2.28 283.043,45.508 286.328,48.793 307.07,48.793 313.334,55.057 313.334,65.557 H8.16
NetFPC2_29: FPC2.29 H8.14 | length 56.4
  Top Layer w0.203: FPC2.29 283.591,43.863 283.591,45.589 286.465,48.463 307.207,48.463 313.665,54.921 313.665,63.348 H8.14
NetFPC2_30: FPC2.30 H8.12 | length 53.7
  Top Layer w0.203: FPC2.30 284.092,43.863 284.092,45.623 286.602,48.133 307.344,48.133 313.995,54.784 313.995,61.138 H8.12
NetFPC2_31: FPC2.31 H8.10 | length 50.9
  Top Layer w0.203: FPC2.31 284.543,45.607 286.739,47.803 307.481,47.803 314.325,54.647 314.325,58.928 H8.10
NetFPC2_32: FPC2.32 H8.8 | length 48.2
  Top Layer w0.203: FPC2.32 285.043,45.64 286.875,47.473 307.617,47.473 314.655,54.51 314.655,56.718 H8.8
NetFPC2_33: FPC2.33 H8.6 | length 45.4
  Top Layer w0.203: FPC2.33 285.591,43.863 285.591,45.722 286.987,47.117 307.729,47.117 322.326,61.714 H8.6
NetH0_2: H0.2 H1.37 H2.37 H3.37 H4.37 H5.37 H6.37 H7.37 H8.37 | length 141.6
  Top Layer w0.203: v1(213.106,107.188) 216.662,103.632 223.012,103.632 H1.37 230.32,102.489 231.463,103.632 237.399,103.632 H2.37 244.707,102.489 245.85,103.632 251.787,103.632 H3.37 258.741,102.489 259.884,103.632 266.174,103.632 H4.37 273.482,102.489 274.625,103.632 280.561,103.632 H5.37 287.515,102.489 288.658,103.632 294.948,103.632 H6.37 301.903,102.489 303.046,103.632 309.336,103.632 H7.37 316.29,102.489 317.433,103.632 323.723,103.632 H8.37
  Top Layer w0.254: H0.2 H0.2@193.531,104.14
  Bottom Layer w0.203: H0.2 196.342,107.188 v1(213.106,107.188)
NetH0_3: H0.3 H1.39 H2.39 H3.39 H4.39 H5.39 H6.39 H7.39 H8.39 | length 139.4
  Top Layer w0.203: H1.39 230.32,105.029 231.59,106.299 237.272,106.299 H2.39 244.354,105.029 245.624,106.299 251.66,106.299 H3.39 258.741,105.029 260.011,106.299 266.047,106.299 H4.39 268.587,106.299 280.434,106.299 H5.39 287.515,105.029 288.785,106.299 294.821,106.299 H6.39 302.256,105.029 303.653,106.426 309.082,106.426 H7.39 316.29,105.029 317.687,106.426 323.469,106.426 H8.39
  Bottom Layer w0.203: H0.3 198.247,106.553 210.693,106.553 213.614,103.632 222.758,103.632 H1.39
NetH0_4: H0.4 H1.31 H2.31 H3.31 H4.31 H5.31 H6.31 H7.31 H8.31 | length 140.8
  Top Layer w0.203: H1.31 229.966,94.869 231.033,93.802 237.475,93.802 H2.31 244.354,94.869 245.42,93.802 251.863,93.802 H3.31 258.741,94.869 259.808,93.802 266.25,93.802 H4.31 273.128,94.869 274.195,93.802 280.637,93.802 H5.31 282.733,93.84 295.063,93.84 H6.31 301.903,94.869 303.046,93.726 309.336,93.726 H7.31 316.29,94.869 317.56,93.599 323.596,93.599 H8.31
  Bottom Layer w0.203: H0.4 211.328,91.186 222.25,91.186 222.933,91.869 222.933,93.647 H1.31
NetH0_5: H0.5 H1.34 | length 32.3
  Bottom Layer w0.203: H0.5 200.914,104.394 202.311,105.791 203.835,105.791 204.724,104.902 204.724,99.822 212.344,92.202 216.408,92.202 H1.34
NetH0_6: H0.6 H1.32 H2.32 H3.32 H4.32 H5.32 H6.32 H7.32 H8.32 | length 135
  Top Layer w0.203: H1.32 222.885,96.139 234.732,96.139 H2.32 237.145,96.012 249.247,96.012 H3.32 251.66,96.139 263.507,96.139 H4.32 265.049,94.869 266.319,96.139 277.894,96.139 H5.32 279.4,94.869 280.67,96.139 292.281,96.139 H6.32 294.821,96.139 306.669,96.139 H7.32 309.209,96.139 321.056,96.139 H8.32
  Bottom Layer w0.203: H0.6 203.454,100.076 211.836,91.694 218.44,91.694 H1.32
NetH0_7: H0.7 H1.29 | length 23.1
  Top Layer w0.203: H0.7 216.408,93.726 222.758,93.726 H1.29
NetH0_9: H0.9 H1.33 H2.33 H3.33 H4.33 H5.33 H6.33 H7.33 H8.33 | length 122.5
  Top Layer w0.203: H0.9 213.106,104.14 218.694,98.552 223.012,98.552 H1.33 229.966,97.409 230.995,98.438 237.514,98.438 H2.33 244.354,97.409 245.382,98.438 251.901,98.438 H3.33 258.741,97.409 259.77,98.438 266.288,98.438 H4.33 273.128,97.409 274.157,98.438 280.676,98.438 H5.33 287.515,97.409 288.544,98.438 295.063,98.438 H6.33 301.903,97.409 302.931,98.438 309.45,98.438 H7.33 316.644,97.409 317.672,98.438 323.837,98.438 H8.33
NetH1_26: H1.26 H2.25 LED2.1 | length 53.2
  Top Layer w0.203: v1(218.313,113.665) 221.107,113.665 LED2.1 ; H1.26 222.758,86.106 v1(229.87,86.106) 237.399,86.106 H2.25
  Bottom Layer w0.203: v1(218.313,113.665) 229.87,102.108 v1(229.87,86.106)
NetH1_30: H1.30 H2.29 R5.2 | length 21
  Top Layer w0.203: H1.30 222.758,91.186 237.399,91.186 H2.29
  Bottom Layer w0.203: H2.29 241.672,92.329 R5.2
NetH1_38: H1.38 H2.38 H3.38 H4.38 H5.38 H6.38 H7.38 H8.38 X1.3 | length 117.2
  Top Layer w0.203: H1.38 222.644,101.46 234.974,101.46 H2.38 236.22,102.489 237.363,101.346 249.247,101.346 H3.38 251.533,101.346 263.634,101.346 H4.38 265.92,101.346 278.021,101.346 H5.38 280.307,101.346 292.408,101.346 H6.38 294.694,101.346 306.796,101.346 H7.38 309.082,101.346 321.183,101.346 H8.38
  Bottom Layer w0.254: X1.3 213.63,97.878 218.241,102.489 H1.38
NetH2_26: H2.26 H3.25 LED3.1 | length 55.8
  Top Layer w0.203: v1(230.632,113.919) 235.512,113.919 LED3.1 ; H2.26 237.145,88.392 251.787,88.392 H3.25
  Bottom Layer w0.203: v1(230.632,113.919) 235.331,109.22 238.252,109.22 244.197,103.275 v1(244.197,88.387)
NetH2_30: H2.30 H3.29 R7.2 | length 22.1
  Top Layer w0.203: H2.30 237.145,93.472 242.969,93.472 245.255,91.186 251.787,91.186 H3.29
  Bottom Layer w0.203: H3.29 R7.2
NetH3_26: H3.26 H4.25 LED4.1 | length 58.7
  Top Layer w0.203: v1(244.983,113.792) LED4.1 ; H3.26 251.533,86.106 v1(258.572,86.106) 266.174,86.106 H4.25
  Bottom Layer w0.203: v1(244.983,113.792) 249.682,109.093 253.873,109.093 258.572,104.394 v1(258.572,86.106)
NetH3_30: H3.30 H4.29 R9.2 | length 22.1
  Top Layer w0.203: H3.30 251.533,93.472 257.357,93.472 259.643,91.186 266.174,91.186 H4.29
  Bottom Layer w0.203: H4.29 R9.2
NetH4_26: H4.26 H5.25 LED5.1 | length 58.1
  Top Layer w0.203: v1(258.191,113.792) LED5.1 ; H4.26 265.049,87.249 266.192,88.392 v1(273.177,88.392) 280.561,88.392 H5.25
  Bottom Layer w0.203: v1(258.191,113.792) 262.255,113.792 273.177,102.87 v1(273.177,88.392)
NetH4_30: H4.30 H5.29 R11.2 | length 22
  Top Layer w0.203: H4.30 265.92,93.472 271.744,93.472 274.03,91.186 280.561,91.186 H5.29
  Bottom Layer w0.203: H5.29 R11.2
NetH5_26: H5.26 H6.25 LED6.1 | length 60.9
  Top Layer w0.203: v1(272.415,113.919) 278.729,113.919 LED6.1 ; H5.26 280.307,86.106 v1(287.628,86.106) 294.948,86.106 H6.25
  Bottom Layer w0.203: v1(272.415,113.919) 277.495,108.839 281.686,108.839 287.628,102.897 v1(287.628,86.106)
NetH5_30: H5.30 H6.29 R13.2 | length 21.1
  Top Layer w0.203: H5.30 280.307,93.472 294.948,93.472 H6.29
  Bottom Layer w0.203: H6.29 R13.2
NetH6_26: H6.26 H7.25 LED7.1 | length 59.1
  Top Layer w0.203: v1(286.512,113.792) LED7.1 ; H6.26 294.694,88.392 v1(302.015,88.392) 309.336,88.392 H7.25
  Bottom Layer w0.203: v1(286.512,113.792) 291.592,108.712 296.164,108.712 302.015,102.861 v1(302.015,88.392)
NetH6_30: H6.30 H7.29 R15.2 | length 21.3
  Top Layer w0.203: H6.30 294.694,91.186 309.336,91.186 H7.29
  Bottom Layer w0.203: H7.29 313.935,92.329 R15.2
NetH7_26: H7.26 H8.25 LED8.1 | length 61.3
  Top Layer w0.203: v1(301.117,113.792) LED8.1 ; H7.26 309.082,86.106 v1(316.402,86.106) 323.723,86.106 H8.25
  Bottom Layer w0.203: v1(301.117,113.792) 306.324,108.585 311.277,108.585 316.402,103.46 v1(316.402,86.106)
NetH7_30: H7.30 H8.29 R17.2 | length 25.1
  Top Layer w0.203: H7.30 308.229,92.329 309.245,93.345 310.318,93.345 cw(c310.479,92.329) 310.639,93.345 315.74,93.345 315.8,93.285 317.899,91.186 323.723,91.186 H8.29
  Bottom Layer w0.203: R17.2 319.434,92.346 320.594,91.186 323.723,91.186 H8.29
NetH8_26: H8.26 LED9.1 | length 36.3
  Top Layer w0.203: v1(315.722,113.792) LED9.1
  Bottom Layer w0.203: v1(315.722,113.792) 318.008,111.506 318.008,90.424 321.183,87.249 H8.26
NetH8_30: H8.30 R19.2 | length 19
  Top Layer w0.203: H8.30 322.593,92.596 323.101,92.596 324.104,93.599 325.501,93.599 326.136,94.234 326.136,105.881 324.222,107.794 R19.2
NetLED1_2: LED1.2 R3.2 | length 2.9
  Top Layer w0.254: R3.2 209.169,110.888 LED1.2
NetLED2_2: LED2.2 R4.2 | length 3.2
  Top Layer w0.254: LED2.2 223.376,113.751 R4.2
NetLED3_2: LED3.2 R6.2 | length 3.3
  Top Layer w0.203: LED3.2 237.74,110.494 R6.2
NetLED4_2: LED4.2 R8.2 | length 3.4
  Top Layer w0.203: R8.2 252.145,110.413 LED4.2
NetLED5_2: LED5.2 R10.2 | length 3.6
  Top Layer w0.203: LED5.2 266.551,110.258 R10.2
NetLED6_2: LED6.2 R12.2 | length 3.7
  Top Layer w0.203: R12.2 280.924,113.76 LED6.2
NetLED7_2: LED7.2 R14.2 | length 3.8
  Top Layer w0.203: LED7.2 295.362,110.022 R14.2
NetLED8_2: LED8.2 R16.2 | length 3.9
  Top Layer w0.203: R16.2 309.744,113.769 LED8.2
NetLED9_2: LED9.2 R18.2 | length 4
  Top Layer w0.203: LED9.2 324.231,113.734 R18.2
NetR1_2: 5.5V.4 R1.2 | length 10
  Top Layer w0.508: v1@180.872,89.686 182.098,90.912 5.5V.4@184.112,90.912
  Bottom Layer w0.508: v1(180.848,89.662) 184.502,89.662 186.28,91.44 R1.2 R1.2@186.338,91.44
NetR2_2: 5.5V.10 R2.2 | length 9.1
  Top Layer w0.508: v1@180.749,87.912 180.752,87.908 180.78,87.908 180.783,87.912 5.5V.10@184.112,87.912
  Bottom Layer w0.508: v1(180.721,87.884) R2.2
SRB2: FPC1.35 FPC2.35 H1.21 H2.21 H3.21 H4.21 H5.21 H6.21 H7.21 H8.21 | length 183.9
  Top Layer w0.203: FPC1.35 230.203,46.942 v1(231.521,48.26) ; FPC2.35 286.543,45.37 v1(287.401,46.228)
  Bottom Layer w0.203: H1.21 227.076,82.169 228.219,81.026 231.521,81.026 ; v1(231.521,48.26) 231.521,81.026 ; v1(287.401,46.228) 287.401,82.169 ; H8.21 323.723,81.026 317.787,81.026 316.644,82.169 H7.21 309.336,81.026 303.046,81.026 301.903,82.169 H6.21 294.948,81.026 290.195,81.026 289.052,82.169 287.401,82.169 ; 231.521,81.026 237.399,81.026 H2.21 244.354,82.169 245.624,80.899 251.66,80.899 H3.21 259.095,82.169 260.238,81.026 266.174,81.026 H4.21 273.128,82.169 274.271,81.026 280.561,81.026 H5.21 287.401,82.169
VBAT: 5.5V.2 5.5V.11 C1.2 U1.1 U1.3 | length 19.4
  Top Layer w0.508: 5.5V.11@184.112,87.262 185.56,87.262 186.309,88.011 186.309,92.068 ; 5.5V.2@184.112,92.062 184.119,92.068 186.309,92.068 ; U1.3@192.09,92.029 192.044,92.075 C1.2 189.096,92.068 186.309,92.068 ; U1.3@192.09,92.178 U1.3 192.136,91.932 192.136,90.722 192.434,90.424 193.692,90.424 193.99,90.722 U1.1
pads on no net: 5.5V.3 5.5V.5 5.5V.6 5.5V.7 5.5V.8 5.5V.9 5.5V.13 5.5V.14 FPC1.41 FPC1.42 FPC2.41 FPC2.42 H1.5 H1.7 H1.9 H1.11 H1.13 H1.15 H1.17 H1.19 H1.22 H2.5 H2.7 H2.9 H2.11 H2.13 H2.15 H2.17 H2.19 H2.22 H2.34 H3.5 H3.7 H3.9 H3.11 H3.13 H3.15 H3.17 H3.19 H3.22 H3.34 H4.5 H4.7 H4.9 H4.11 H4.13 H4.15 H4.17 H4.19 H4.22 H4.34 H5.5 H5.7 H5.9 H5.11 H5.13 H5.15 H5.17 H5.19 H5.22 H5.34 H6.5 H6.7 H6.9 H6.11 H6.13 H6.15 H6.17 H6.19 H6.22 H6.34 H7.5 H7.7 H7.9 H7.11 H7.13 H7.15 H7.17 H7.19 H7.22 H7.34 H8.5 H8.7 H8.9 H8.11 H8.13 H8.15 H8.17 H8.19 H8.22 H8.34 U1.4 U3.4
copper on no net:
  other v3: 181.737,41.148 329.946,41.148 181.737,116.205 329.946,116.205

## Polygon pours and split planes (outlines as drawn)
GND on Top Layer "GND_L01_P000" (solid, pour order 0): 177.673,41.148 177.673,116.205 177.671,116.205 cw(c181.737,116.205) 181.737,120.271 181.737,120.269 329.942,120.269 329.944,120.271 cw(c329.944,116.205) 334.01,116.205 334.01,41.15 334.012,41.148 cw(c329.946,41.148) 329.946,37.082 181.737,37.082 cw(c181.737,41.148)
GND on Bottom Layer "GND_L06_P001" (solid, pour order 1): 177.673,41.148 177.673,116.205 177.671,116.205 cw(c181.737,116.205) 181.737,120.271 181.737,120.269 329.942,120.269 329.944,120.271 cw(c329.944,116.205) 334.01,116.205 334.01,41.15 334.012,41.148 cw(c329.946,41.148) 329.946,37.082 181.737,37.082 cw(c181.737,41.148)
GND on GND (split plane): 330.639,119.7 331.089,119.579 331.52,119.401 331.924,119.168 332.293,118.884 332.623,118.554 332.907,118.185 333.14,117.781 333.318,117.35 333.439,116.9 333.5,116.438 333.5,116.205 333.502,41.148 333.502,40.915 333.441,40.453 333.32,40.003 333.142,39.572 332.909,39.168 332.625,38.799 332.295,38.469 331.926,38.185 331.522,37.952 331.091,37.774 330.641,37.653 330.179,37.592 181.504,37.592 181.042,37.653 180.592,37.774 180.161,37.952 179.757,38.185 179.388,38.469 179.058,38.799 178.774,39.168 178.541,39.572 178.363,40.003 178.242,40.453 178.182,40.913 178.183,41.144 178.183,41.146 178.183,41.148 178.181,116.205 178.181,116.438 178.242,116.9 178.363,117.35 178.541,117.781 178.774,118.185 179.058,118.554 179.388,118.884 179.757,119.168 180.161,119.401 180.592,119.579 181.042,119.7 181.502,119.76 181.733,119.759 181.735,119.759 181.737,119.759 329.944,119.761 330.177,119.761
AVSS on AVSS (split plane): 330.639,119.7 331.089,119.579 331.52,119.401 331.924,119.168 332.293,118.884 332.623,118.554 332.907,118.185 333.14,117.781 333.318,117.35 333.439,116.9 333.5,116.438 333.5,116.205 333.502,41.148 333.502,40.915 333.441,40.453 333.32,40.003 333.142,39.572 332.909,39.168 332.625,38.799 332.295,38.469 331.926,38.185 331.522,37.952 331.091,37.774 330.641,37.653 330.179,37.592 181.504,37.592 181.042,37.653 180.592,37.774 180.161,37.952 179.757,38.185 179.388,38.469 179.058,38.799 178.774,39.168 178.541,39.572 178.363,40.003 178.242,40.453 178.182,40.913 178.183,41.144 178.183,41.146 178.183,41.148 178.181,116.205 178.181,116.438 178.242,116.9 178.363,117.35 178.541,117.781 178.774,118.185 179.058,118.554 179.388,118.884 179.757,119.168 180.161,119.401 180.592,119.579 181.042,119.7 181.502,119.76 181.733,119.759 181.735,119.759 181.737,119.759 329.944,119.761 330.177,119.761
AVDD on AVDD (split plane): 330.639,119.7 331.089,119.579 331.52,119.401 331.924,119.168 332.293,118.884 332.623,118.554 332.907,118.185 333.14,117.781 333.318,117.35 333.439,116.9 333.5,116.438 333.5,116.205 333.502,41.148 333.502,40.915 333.441,40.453 333.32,40.003 333.142,39.572 332.909,39.168 332.625,38.799 332.295,38.469 331.926,38.185 331.522,37.952 331.091,37.774 330.641,37.653 330.179,37.592 181.504,37.592 181.042,37.653 180.592,37.774 180.161,37.952 179.757,38.185 179.388,38.469 179.058,38.799 178.774,39.168 178.541,39.572 178.363,40.003 178.242,40.453 178.182,40.913 178.183,41.144 178.183,41.146 178.183,41.148 178.181,116.205 178.181,116.438 178.242,116.9 178.363,117.35 178.541,117.781 178.774,118.185 179.058,118.554 179.388,118.884 179.757,119.168 180.161,119.401 180.592,119.579 181.042,119.7 181.502,119.76 181.733,119.759 181.735,119.759 181.737,119.759 329.944,119.761 330.177,119.761
DVDD on DVDD (split plane): 330.639,119.7 331.089,119.579 331.52,119.401 331.924,119.168 332.293,118.884 332.623,118.554 332.907,118.185 333.14,117.781 333.318,117.35 333.439,116.9 333.5,116.438 333.5,116.205 333.502,41.148 333.502,40.915 333.441,40.453 333.32,40.003 333.142,39.572 332.909,39.168 332.625,38.799 332.295,38.469 331.926,38.185 331.522,37.952 331.091,37.774 330.641,37.653 330.179,37.592 181.504,37.592 181.042,37.653 180.592,37.774 180.161,37.952 179.757,38.185 179.388,38.469 179.058,38.799 178.774,39.168 178.541,39.572 178.363,40.003 178.242,40.453 178.182,40.913 178.183,41.144 178.183,41.146 178.183,41.148 178.181,116.205 178.181,116.438 178.242,116.9 178.363,117.35 178.541,117.781 178.774,118.185 179.058,118.554 179.388,118.884 179.757,119.168 180.161,119.401 180.592,119.579 181.042,119.7 181.502,119.76 181.733,119.759 181.735,119.759 181.737,119.759 329.944,119.761 330.177,119.761

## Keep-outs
Keep-Out Layer:
  lines w0.254: 177.671,41.148 ccw(c181.737,41.148) 181.737,37.082 ; 177.671,116.205 cw(c181.737,116.205) 181.737,120.271 ; 177.673,41.148 177.673,116.205 ; 181.737,120.269 329.942,120.269 ; 181.739,37.082 329.946,37.082 ccw(c329.946,41.148) 334.012,41.148 ; 329.944,120.271 cw(c329.944,116.205) 334.01,116.205 334.01,41.15

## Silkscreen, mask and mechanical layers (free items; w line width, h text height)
Top Overlay:
  drawing of 16 lines, arcs and shapes, not listed
  text "CS" at 193.652,100.734 h0.8 r90
  text "GND" at 208.892,99.972 h0.8 r90
  text "MOSI" at 203.812,99.464 h0.8 r90
  text "MISO" at 206.352,99.337 h0.8 r90
  text "DVDD" at 191.112,99.21 h0.8 r90
  text "PWDN" at 196.192,99.21 h0.8 r90
  text "DRDY" at 201.272,99.21 h0.8 r90
  text "SCLK" at 211.432,99.21 h0.8 r90
  text "RESET" at 198.859,98.575 h0.8 r90
  text "IMECAS" at 187.071,51.181 h1.22
  text "e" at 307.812,38.297 h10.31
Bottom Overlay:
  text "Ver.lpb20240201" at 326.39,40.386 h1.52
